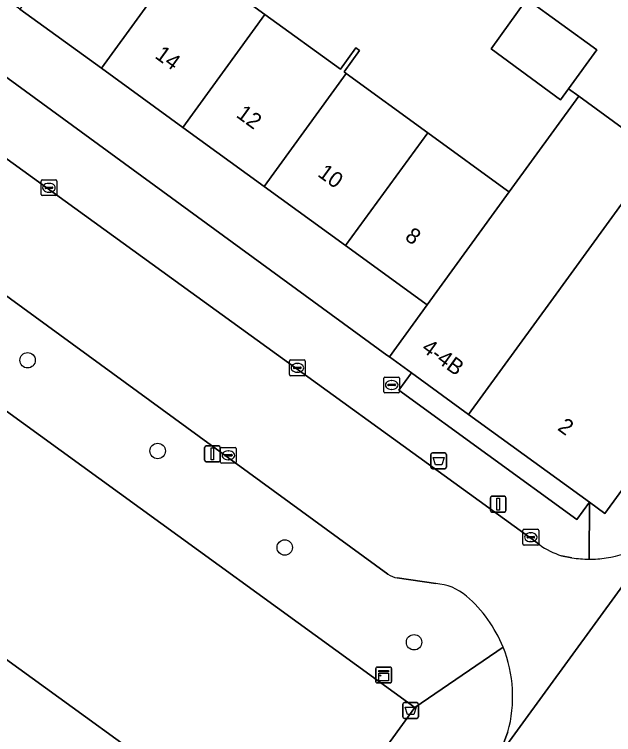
# Model space of a CAD drawing. Extents: x 159674 to 160531, y 382172 to 382904.
# Drawn here: x 160137.75 to 160175.73, y 382438.2 to 382483.87 of the extents above; entities that cross this region are included whole.
import ezdxf

# ---------------------------------------------------------------- set-up
doc = ezdxf.new("R2010")
doc.units = 0
for name, color, linetype in [('IMGEO_Afvalbak', 7, 'Continuous'), ('IMGEO_Boom', 7, 'Continuous'), ('IMGEO_Brandkraan', 7, 'Continuous'), ('IMGEO_Erf', 7, 'Continuous'), ('IMGEO_Kast', 7, 'Continuous'), ('IMGEO_Kolk', 7, 'Continuous'), ('IMGEO_Lichtmast', 7, 'Continuous'), ('IMGEO_Pand', 7, 'Continuous'), ('IMGEO_Pand_nummerreeks', 7, 'Continuous'), ('IMGEO_Rijbaan_lokaal_gesloten', 7, 'Continuous'), ('IMGEO_Rijbaan_lokaal_open', 7, 'Continuous'), ('IMGEO_Voetpad_open', 7, 'Continuous')]:
    doc.layers.add(name, color=color, linetype=linetype)

msp = doc.modelspace()

# ---------------------------------------------------------------- linework, layer by layer
at = {"layer": 'IMGEO_Afvalbak'}
for p, q in [((160164.246, 382456.061), (160165.036, 382456.061)), ((160165.036, 382456.061), (160164.246, 382456.061)), ((160164.146, 382455.161), (160164.146, 382455.961)), ((160164.146, 382455.961), (160164.146, 382455.161)), ((160165.136, 382455.961), (160165.136, 382455.161)), ((160165.136, 382455.161), (160165.136, 382455.961)), ((160165.036, 382455.061), (160164.246, 382455.061)), ((160164.246, 382455.061), (160165.036, 382455.061)), ((160162.369, 382439.328), (160162.369, 382440.128)), ((160162.369, 382440.128), (160162.369, 382439.328)), ((160162.469, 382440.228), (160163.259, 382440.228)), ((160163.259, 382440.228), (160162.469, 382440.228)), ((160163.359, 382440.128), (160163.359, 382439.328)), ((160163.359, 382439.328), (160163.359, 382440.128)), ((160163.259, 382439.228), (160162.469, 382439.228)), ((160162.469, 382439.228), (160163.259, 382439.228))]:
    msp.add_line(p, q, dxfattribs=at)
for points in [[(160164.289, 382455.775), (160164.993, 382455.775), (160164.844, 382455.305), (160164.438, 382455.305), (160164.289, 382455.775)], [(160162.512, 382439.942), (160163.216, 382439.942), (160163.067, 382439.472), (160162.661, 382439.472), (160162.512, 382439.942)]]:
    msp.add_lwpolyline(points, dxfattribs=at)
for centre, start, end in [((160164.246, 382455.961), 90, 180), ((160164.246, 382455.961), 90, 180), ((160165.036, 382455.961), 0, 90), ((160165.036, 382455.961), 360, 90), ((160164.246, 382455.161), 180, 270), ((160164.246, 382455.161), 180, 270), ((160165.036, 382455.161), 270, 0), ((160165.036, 382455.161), 270, 0), ((160162.469, 382440.128), 90, 180), ((160162.469, 382440.128), 90, 180), ((160163.259, 382440.128), 0, 90), ((160163.259, 382440.128), 360, 90), ((160162.469, 382439.328), 180, 270), ((160162.469, 382439.328), 180, 270), ((160163.259, 382439.328), 270, 0), ((160163.259, 382439.328), 270, 0)]:
    msp.add_arc(centre, 0.1, start, end, dxfattribs=at)
at = {"layer": 'IMGEO_Boom'}
for centre in [(160138.58, 382461.94), (160146.827, 382456.187), (160154.885, 382450.065), (160163.082, 382444.058)]:
    msp.add_circle(centre, 0.489, dxfattribs=at)
at = {"layer": 'IMGEO_Brandkraan'}
for p, q in [((160161.163, 382459.947), (160161.163, 382460.799)), ((160161.238, 382460.873), (160162.09, 382460.873)), ((160161.651, 382460.653), (160161.676, 382460.653)), ((160162.164, 382460.799), (160162.164, 382459.947)), ((160161.422, 382460.367), (160161.422, 382460.379)), ((160161.86, 382460.33), (160161.462, 382460.33)), ((160161.465, 382460.416), (160161.863, 382460.416)), ((160161.674, 382460.093), (160161.649, 382460.093)), ((160161.906, 382460.379), (160161.906, 382460.367)), ((160162.09, 382459.873), (160161.238, 382459.873))]:
    msp.add_line(p, q, dxfattribs=at)
for points in [[(160161.163, 382459.947), (160161.163, 382460.799)], [(160161.238, 382460.873), (160162.09, 382460.873)], [(160162.164, 382460.799), (160162.164, 382459.947)], [(160162.09, 382459.873), (160161.238, 382459.873)]]:
    msp.add_lwpolyline(points, dxfattribs=at)
for centre, radius, start, end in [((160161.24, 382460.797), 0.0765, 91.552, 178.448), ((160161.24, 382460.797), 0.0765, 91.552, 178.448), ((160162.088, 382460.797), 0.0765, 1.552, 88.448), ((160162.088, 382460.797), 0.0765, 1.552, 88.448), ((160161.462, 382460.376), 0.0403, 85.8775, 175.7526), ((160161.459, 382460.366), 0.0366, 178.938, 274.7102), ((160161.863, 382460.373), 0.043, 264.8664, 352.4533), ((160161.867, 382460.378), 0.0386, 1.7309, 96.639), ((160161.24, 382459.949), 0.0765, 181.552, 268.448), ((160161.24, 382459.949), 0.0765, 181.552, 268.448), ((160162.088, 382459.949), 0.0765, 271.552, 358.448), ((160162.088, 382459.949), 0.0765, 271.552, 358.448)]:
    msp.add_arc(centre, radius, start, end, dxfattribs=at)
for centre, major_axis, ratio, start_param, end_param in [((160161.65, 382460.373), (-0.387, 0.002), 0.722429, 4.712389, 7.853982), ((160161.675, 382460.373), (-0.39, 0.002), 0.717154, 1.570796, 4.712389)]:
    msp.add_ellipse(centre, major_axis=major_axis, ratio=ratio, start_param=start_param, end_param=end_param, dxfattribs=at)
at = {"layer": 'IMGEO_Erf'}
msp.add_lwpolyline([(160143.26, 382480.459), (160138.099, 382484.21), (160132.938, 382487.961), (160127.653, 382491.801), (160125.316, 382488.609), (160161.358, 382462.265), (160161.521, 382462.147), (160163.916, 382465.448), (160163.756, 382465.564), (160158.743, 382469.207), (160153.582, 382472.958), (160148.42, 382476.709)], close=True, dxfattribs=at)
for points in [[(160127.601, 382390.967), (160163.121, 382439.912), (160095.853, 382488.776)], [(160148.464, 382487.621), (160153.625, 382483.87), (160158.409, 382480.393), (160159.392, 382481.746), (160159.625, 382481.576), (160158.641, 382480.223), (160158.785, 382480.118), (160163.946, 382476.367), (160169.012, 382472.685), (160169.115, 382472.611), (160173.525, 382478.688), (160172.878, 382479.162), (160172.364, 382478.461), (160167.97, 382481.681), (160170.234, 382484.868)], [(160096.525, 382483.765), (160111.322, 382472.965), (160111.135, 382472.707), (160109.272, 382474.068), (160105.385, 382468.743), (160107.249, 382467.383), (160114.61, 382462.01), (160113.991, 382461.163), (160115.428, 382460.113), (160116.047, 382460.961), (160120.344, 382457.824), (160123.697, 382458.347), (160127.897, 382455.282), (160128.423, 382451.931), (160135.628, 382446.672), (160134.121, 382444.607), (160134.283, 382444.49), (160133.836, 382443.873), (160135.578, 382442.609), (160136.317, 382443.627), (160150.083, 382433.637)]]:
    msp.add_lwpolyline(points, dxfattribs=at)
at = {"layer": 'IMGEO_Kast'}
for p, q in [((160160.658, 382441.551), (160160.658, 382442.392)), ((160160.658, 382442.392), (160160.658, 382441.551)), ((160160.733, 382442.476), (160161.574, 382442.476)), ((160161.574, 382442.476), (160160.733, 382442.476)), ((160161.658, 382442.401), (160161.658, 382441.56)), ((160161.658, 382441.56), (160161.658, 382442.401)), ((160161.583, 382441.476), (160160.742, 382441.476)), ((160160.742, 382441.476), (160161.583, 382441.476))]:
    msp.add_line(p, q, dxfattribs=at)
for points in [[(160160.853, 382442.266), (160161.453, 382442.266), (160161.453, 382442.181), (160160.853, 382442.181), (160160.853, 382442.266)], [(160160.853, 382442.091), (160161.453, 382442.091), (160161.453, 382441.602), (160160.853, 382441.602), (160160.853, 382442.091)]]:
    msp.add_lwpolyline(points, dxfattribs=at)
msp.add_circle((160160.937, 382441.94), 0.0377, dxfattribs=at)
for centre, start, end in [((160160.736, 382442.398), 92.4484, 184.2845), ((160160.736, 382442.398), 92.4484, 184.2845), ((160161.58, 382442.398), 2.4484, 94.2845), ((160161.58, 382442.398), 2.4484, 94.2845), ((160160.736, 382441.554), 182.4484, 274.2845), ((160160.736, 382441.554), 182.4484, 274.2845), ((160161.58, 382441.554), 272.4484, 4.2845), ((160161.58, 382441.554), 272.4484, 4.2845)]:
    msp.add_arc(centre, 0.0779, start, end, dxfattribs=at)
at = {"layer": 'IMGEO_Kolk'}
for p, q in [((160139.507, 382473.378), (160140.359, 382473.378)), ((160139.432, 382472.452), (160139.432, 382473.304)), ((160139.691, 382472.872), (160139.691, 382472.884)), ((160139.734, 382472.921), (160140.132, 382472.921)), ((160139.92, 382473.158), (160139.945, 382473.158)), ((160140.175, 382472.884), (160140.175, 382472.872)), ((160140.433, 382473.304), (160140.433, 382472.452)), ((160140.129, 382472.835), (160139.731, 382472.835)), ((160139.943, 382472.598), (160139.918, 382472.598)), ((160140.359, 382472.378), (160139.507, 382472.378)), ((160155.26, 382461.959), (160156.112, 382461.959)), ((160155.185, 382461.033), (160155.185, 382461.885)), ((160155.444, 382461.453), (160155.444, 382461.465)), ((160155.487, 382461.502), (160155.885, 382461.502)), ((160155.673, 382461.739), (160155.698, 382461.739)), ((160155.928, 382461.465), (160155.928, 382461.453)), ((160156.186, 382461.885), (160156.186, 382461.033)), ((160155.882, 382461.416), (160155.484, 382461.416)), ((160155.696, 382461.179), (160155.671, 382461.179)), ((160156.112, 382460.959), (160155.26, 382460.959)), ((160150.813, 382455.485), (160150.813, 382456.337)), ((160150.888, 382456.411), (160151.74, 382456.411)), ((160151.301, 382456.191), (160151.326, 382456.191)), ((160151.814, 382456.337), (160151.814, 382455.485)), ((160151.072, 382455.905), (160151.072, 382455.917)), ((160151.51, 382455.868), (160151.112, 382455.868)), ((160151.115, 382455.954), (160151.513, 382455.954)), ((160151.324, 382455.631), (160151.299, 382455.631)), ((160151.556, 382455.917), (160151.556, 382455.905)), ((160151.74, 382455.411), (160150.888, 382455.411)), ((160169.982, 382450.292), (160169.982, 382451.144)), ((160170.057, 382451.218), (160170.909, 382451.218)), ((160170.47, 382450.998), (160170.495, 382450.998)), ((160170.983, 382451.144), (160170.983, 382450.292)), ((160170.241, 382450.712), (160170.241, 382450.724)), ((160170.679, 382450.675), (160170.281, 382450.675)), ((160170.284, 382450.761), (160170.682, 382450.761)), ((160170.725, 382450.724), (160170.725, 382450.712)), ((160170.909, 382450.218), (160170.057, 382450.218)), ((160170.493, 382450.438), (160170.468, 382450.438))]:
    msp.add_line(p, q, dxfattribs=at)
for points in [[(160139.507, 382473.378), (160140.359, 382473.378)], [(160139.432, 382472.452), (160139.432, 382473.304)], [(160140.433, 382473.304), (160140.433, 382472.452)], [(160140.359, 382472.378), (160139.507, 382472.378)], [(160155.26, 382461.959), (160156.112, 382461.959)], [(160155.185, 382461.033), (160155.185, 382461.885)], [(160156.186, 382461.885), (160156.186, 382461.033)], [(160156.112, 382460.959), (160155.26, 382460.959)], [(160150.813, 382455.485), (160150.813, 382456.337)], [(160150.888, 382456.411), (160151.74, 382456.411)], [(160151.814, 382456.337), (160151.814, 382455.485)], [(160151.74, 382455.411), (160150.888, 382455.411)], [(160169.982, 382450.292), (160169.982, 382451.144)], [(160170.057, 382451.218), (160170.909, 382451.218)], [(160170.983, 382451.144), (160170.983, 382450.292)], [(160170.909, 382450.218), (160170.057, 382450.218)]]:
    msp.add_lwpolyline(points, dxfattribs=at)
for centre, radius, start, end in [((160139.509, 382473.302), 0.0765, 91.552, 178.448), ((160139.509, 382473.302), 0.0765, 91.552, 178.448), ((160140.357, 382473.302), 0.0765, 1.552, 88.448), ((160140.357, 382473.302), 0.0765, 1.552, 88.448), ((160139.731, 382472.881), 0.0403, 85.8775, 175.7526), ((160140.136, 382472.883), 0.0386, 1.7309, 96.639), ((160139.509, 382472.454), 0.0765, 181.552, 268.448), ((160139.509, 382472.454), 0.0765, 181.552, 268.448), ((160139.728, 382472.871), 0.0366, 178.938, 274.7102), ((160140.132, 382472.878), 0.043, 264.8664, 352.4533), ((160140.357, 382472.454), 0.0765, 271.552, 358.448), ((160140.357, 382472.454), 0.0765, 271.552, 358.448), ((160155.262, 382461.883), 0.0765, 91.552, 178.448), ((160155.262, 382461.883), 0.0765, 91.552, 178.448), ((160156.11, 382461.883), 0.0765, 1.552, 88.448), ((160156.11, 382461.883), 0.0765, 1.552, 88.448), ((160155.484, 382461.462), 0.0403, 85.8775, 175.7526), ((160155.889, 382461.464), 0.0386, 1.7309, 96.639), ((160155.262, 382461.035), 0.0765, 181.552, 268.448), ((160155.262, 382461.035), 0.0765, 181.552, 268.448), ((160155.481, 382461.452), 0.0366, 178.938, 274.7102), ((160155.885, 382461.459), 0.043, 264.8664, 352.4533), ((160156.11, 382461.035), 0.0765, 271.552, 358.448), ((160156.11, 382461.035), 0.0765, 271.552, 358.448), ((160150.89, 382456.335), 0.0765, 91.552, 178.448), ((160150.89, 382456.335), 0.0765, 91.552, 178.448), ((160151.738, 382456.335), 0.0765, 1.552, 88.448), ((160151.738, 382456.335), 0.0765, 1.552, 88.448), ((160151.112, 382455.914), 0.0403, 85.8775, 175.7526), ((160151.109, 382455.904), 0.0366, 178.938, 274.7102), ((160151.513, 382455.911), 0.043, 264.8664, 352.4533), ((160151.517, 382455.916), 0.0386, 1.7309, 96.639), ((160150.89, 382455.487), 0.0765, 181.552, 268.448), ((160150.89, 382455.487), 0.0765, 181.552, 268.448), ((160151.738, 382455.487), 0.0765, 271.552, 358.448), ((160151.738, 382455.487), 0.0765, 271.552, 358.448), ((160170.059, 382451.142), 0.0765, 91.552, 178.448), ((160170.059, 382451.142), 0.0765, 91.552, 178.448), ((160170.907, 382451.142), 0.0765, 1.552, 88.448), ((160170.907, 382451.142), 0.0765, 1.552, 88.448), ((160170.281, 382450.721), 0.0403, 85.8775, 175.7526), ((160170.278, 382450.711), 0.0366, 178.938, 274.7102), ((160170.682, 382450.718), 0.043, 264.8664, 352.4533), ((160170.686, 382450.723), 0.0386, 1.7309, 96.639), ((160170.059, 382450.294), 0.0765, 181.552, 268.448), ((160170.059, 382450.294), 0.0765, 181.552, 268.448), ((160170.907, 382450.294), 0.0765, 271.552, 358.448), ((160170.907, 382450.294), 0.0765, 271.552, 358.448)]:
    msp.add_arc(centre, radius, start, end, dxfattribs=at)
for centre, major_axis, ratio, start_param, end_param in [((160139.919, 382472.878), (-0.387, 0.002), 0.722429, 4.712389, 7.853982), ((160139.944, 382472.878), (-0.39, 0.002), 0.717154, 1.570796, 4.712389), ((160155.672, 382461.459), (-0.387, 0.002), 0.722429, 4.712389, 7.853982), ((160155.697, 382461.459), (-0.39, 0.002), 0.717154, 1.570796, 4.712389), ((160151.3, 382455.911), (-0.387, 0.002), 0.722429, 4.712389, 7.853982), ((160151.325, 382455.911), (-0.39, 0.002), 0.717154, 1.570796, 4.712389), ((160170.469, 382450.718), (-0.387, 0.002), 0.722429, 4.712389, 7.853982), ((160170.494, 382450.718), (-0.39, 0.002), 0.717154, 1.570796, 4.712389)]:
    msp.add_ellipse(centre, major_axis=major_axis, ratio=ratio, start_param=start_param, end_param=end_param, dxfattribs=at)
at = {"layer": 'IMGEO_Lichtmast'}
for p, q in [((160149.907, 382456.507), (160150.697, 382456.507)), ((160150.697, 382456.507), (160149.907, 382456.507)), ((160149.807, 382455.607), (160149.807, 382456.407)), ((160149.807, 382456.407), (160149.807, 382455.607)), ((160150.797, 382456.407), (160150.797, 382455.607)), ((160150.797, 382455.607), (160150.797, 382456.407)), ((160150.697, 382455.507), (160149.907, 382455.507)), ((160149.907, 382455.507), (160150.697, 382455.507)), ((160168.018, 382453.314), (160168.808, 382453.314)), ((160168.808, 382453.314), (160168.018, 382453.314)), ((160167.918, 382452.414), (160167.918, 382453.214)), ((160167.918, 382453.214), (160167.918, 382452.414)), ((160168.908, 382453.214), (160168.908, 382452.414)), ((160168.908, 382452.414), (160168.908, 382453.214)), ((160168.808, 382452.314), (160168.018, 382452.314)), ((160168.018, 382452.314), (160168.808, 382452.314))]:
    msp.add_line(p, q, dxfattribs=at)
for points in [[(160150.227, 382456.382), (160150.377, 382456.382), (160150.377, 382455.632), (160150.227, 382455.632), (160150.227, 382456.382)], [(160168.338, 382453.189), (160168.488, 382453.189), (160168.488, 382452.439), (160168.338, 382452.439), (160168.338, 382453.189)]]:
    msp.add_lwpolyline(points, dxfattribs=at)
for centre, start, end in [((160149.907, 382456.407), 90, 180), ((160149.907, 382456.407), 90, 180), ((160150.697, 382456.407), 0, 90), ((160150.697, 382456.407), 360, 90), ((160149.907, 382455.607), 180, 270), ((160149.907, 382455.607), 180, 270), ((160150.697, 382455.607), 270, 0), ((160150.697, 382455.607), 270, 0), ((160168.018, 382453.214), 90, 180), ((160168.018, 382453.214), 90, 180), ((160168.808, 382453.214), 0, 90), ((160168.808, 382453.214), 360, 90), ((160168.018, 382452.414), 180, 270), ((160168.018, 382452.414), 180, 270), ((160168.808, 382452.414), 270, 0), ((160168.808, 382452.414), 270, 0)]:
    msp.add_arc(centre, 0.1, start, end, dxfattribs=at)
at = {"layer": 'IMGEO_Pand'}
for points in [[(160138.099, 382484.21), (160143.26, 382480.459), (160148.464, 382487.621), (160149.354, 382488.996), (160149.063, 382489.208), (160148.063, 382487.832), (160143.265, 382491.318)], [(160148.42, 382476.709), (160153.625, 382483.87), (160148.464, 382487.621), (160143.26, 382480.459)], [(160170.234, 382484.868), (160167.97, 382481.681), (160172.364, 382478.461), (160172.878, 382479.162), (160174.675, 382481.615)], [(160148.42, 382476.709), (160153.582, 382472.958), (160158.785, 382480.118), (160158.641, 382480.223), (160159.625, 382481.576), (160159.392, 382481.746), (160158.409, 382480.393), (160153.625, 382483.87)], [(160163.946, 382476.367), (160158.785, 382480.118), (160153.582, 382472.958), (160158.743, 382469.207)], [(160176.578, 382472.309), (160178.556, 382475.031), (160176.28, 382476.685), (160173.525, 382478.688), (160169.115, 382472.611), (160163.916, 382465.448), (160161.521, 382462.147), (160162.914, 382461.134), (160166.542, 382458.498), (160171.752, 382465.667)], [(160169.115, 382472.611), (160169.012, 382472.685), (160163.946, 382476.367), (160158.743, 382469.207), (160163.756, 382465.564), (160163.916, 382465.448)], [(160187.174, 382468.769), (160183.129, 382471.708), (160181.626, 382472.8), (160178.556, 382475.031), (160176.578, 382472.309), (160171.752, 382465.667), (160166.542, 382458.498), (160174.199, 382452.933), (160175.186, 382452.216), (160180.126, 382459.014), (160179.103, 382459.758), (160180.065, 382461.082), (160181.061, 382460.357)]]:
    msp.add_lwpolyline(points, close=True, dxfattribs=at)
msp.add_lwpolyline([(160150.083, 382433.637), (160136.317, 382443.627), (160135.578, 382442.609), (160133.836, 382443.873), (160134.283, 382444.49), (160134.121, 382444.607), (160135.628, 382446.672), (160128.423, 382451.931), (160127.897, 382455.282), (160123.697, 382458.347), (160120.344, 382457.824), (160116.047, 382460.961), (160115.428, 382460.113), (160113.991, 382461.163), (160114.61, 382462.01), (160107.249, 382467.383), (160105.385, 382468.743), (160109.272, 382474.068), (160111.135, 382472.707), (160111.322, 382472.965), (160096.525, 382483.765)], dxfattribs=at)
at = {"layer": 'IMGEO_Rijbaan_lokaal_gesloten'}
msp.add_lwpolyline([(160315.311, 382639.622), (160304.717, 382625.008), (160302.639, 382622.143), (160290.62, 382605.563), (160279.709, 382590.612), (160279.414, 382590.208), (160269.482, 382576.534), (160263.507, 382568.309), (160253.466, 382554.485), (160253.079, 382553.951), (160242.339, 382539.119), (160232.376, 382525.365), (160226.58, 382517.362), (160218.061, 382505.6), (160216.652, 382503.655), (160216.208, 382503.063), (160216.121, 382502.946), (160214.024, 382500), (160205.773, 382488.409), (160195.682, 382474.429), (160187.988, 382463.77), (160179.328, 382451.773), (160168.227, 382436.541)], dxfattribs=at)
at = {"layer": 'IMGEO_Rijbaan_lokaal_open'}
for points in [[(160066.041, 382526.373), (160065.761, 382526.548), (160061.728, 382520.822), (160061.99, 382520.627), (160135.135, 382467.543), (160161.419, 382448.379)], [(160171.029, 382450.249), (160148.312, 382466.705), (160086.083, 382511.782), (160066.041, 382526.373)], [(160169.029, 382438.37), (160168.691, 382437.473), (160168.227, 382436.541), (160179.328, 382451.773)], [(160173.092, 382449.416), (160172.437, 382449.547)], [(160162.016, 382448.135), (160164.453, 382447.775)]]:
    msp.add_lwpolyline(points, dxfattribs=at)
for centre, radius, start, end in [((160174.344, 382455.642), 6.309, 278.415, 322.1838), ((160173.818, 382454.08), 4.739, 233.9447, 253.0555), ((160174.225, 382456.571), 7.244, 261.0021, 269.6364), ((160174.239, 382456.58), 7.253, 269.5276, 278.1495), ((160162.283, 382449.64), 1.529, 235.5919, 259.9474), ((160164.268, 382444.526), 3.255, 48.9744, 86.7359), ((160160.946, 382440.613), 8.387, 21.9368, 49.4028), ((160160.935, 382440.61), 8.399, 344.5293, 21.9224)]:
    msp.add_arc(centre, radius, start, end, dxfattribs=at)
at = {"layer": 'IMGEO_Voetpad_open'}
for points in [[(160064.445, 382527.55), (160065.761, 382526.548), (160066.041, 382526.373), (160086.083, 382511.782), (160148.312, 382466.705), (160171.029, 382450.249)], [(160161.419, 382448.379), (160135.135, 382467.543), (160061.99, 382520.627)], [(160174.179, 382449.327), (160174.199, 382452.933), (160173.407, 382451.842), (160162.122, 382460.043), (160162.914, 382461.134), (160161.521, 382462.147), (160161.358, 382462.265), (160125.316, 382488.609), (160127.653, 382491.801), (160126.342, 382492.78), (160125.171, 382491.169), (160124.011, 382489.563), (160122.995, 382488.155), (160106.723, 382500), (160088.55, 382513.229)], [(160095.853, 382488.776), (160163.121, 382439.912), (160168.726, 382443.746)], [(160170.234, 382484.868), (160174.675, 382481.615), (160172.878, 382479.162), (160173.525, 382478.688), (160176.28, 382476.685)], [(160187.988, 382463.77), (160187.039, 382464.471), (160191.984, 382471.373), (160190.085, 382472.747), (160188.874, 382471.092), (160187.611, 382469.366), (160187.174, 382468.769), (160181.061, 382460.357), (160180.065, 382461.082), (160179.103, 382459.758), (160180.126, 382459.014), (160175.186, 382452.216), (160174.199, 382452.933), (160174.179, 382449.327)], [(160172.437, 382449.547), (160173.092, 382449.416)], [(160164.453, 382447.775), (160162.016, 382448.135)], [(160168.726, 382443.746), (160163.121, 382439.912), (160127.601, 382390.967), (160123.455, 382384.426)], [(160167.872, 382436.054), (160168.227, 382436.541), (160168.691, 382437.473), (160169.029, 382438.37)]]:
    msp.add_lwpolyline(points, dxfattribs=at)
msp.add_lwpolyline([(160166.542, 382458.498), (160162.914, 382461.134), (160162.122, 382460.043), (160173.407, 382451.842), (160174.199, 382452.933)], close=True, dxfattribs=at)
for centre, radius, start, end in [((160174.344, 382455.642), 6.309, 278.415, 322.1838), ((160173.818, 382454.08), 4.739, 233.9447, 253.0555), ((160174.225, 382456.571), 7.244, 261.0021, 269.6364), ((160174.239, 382456.58), 7.253, 269.5276, 278.1495), ((160162.283, 382449.64), 1.529, 235.5919, 259.9474), ((160164.268, 382444.526), 3.255, 48.9744, 86.7359), ((160160.946, 382440.613), 8.387, 21.9368, 49.4028), ((160160.935, 382440.61), 8.399, 344.5293, 21.9224)]:
    msp.add_arc(centre, radius, start, end, dxfattribs=at)

# ---------------------------------------------------------------- texts
at = {"layer": 'IMGEO_Pand_nummerreeks'}
for s, rotation, p in [('14', 323.9931, (160146.59, 382481.153)), ('12', 323.9931, (160151.746, 382477.406)), ('10', 323.9931, (160156.909, 382473.655)), ('8', 323.9953, (160162.439, 382469.636)), ('4-4B', 324.0011, (160163.495, 382462.566)), ('2', 323.9953, (160172.121, 382457.558))]:
    msp.add_text(s, height=1, rotation=rotation, dxfattribs=at).set_placement(p)

doc.saveas('drawing.dxf')
